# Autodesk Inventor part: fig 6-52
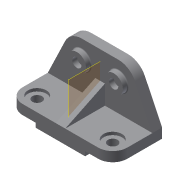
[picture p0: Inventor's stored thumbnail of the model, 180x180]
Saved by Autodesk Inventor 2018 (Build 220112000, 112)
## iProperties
Shininess: 77.0
Length Units: 11269
Angle Units: 11279
Time Units: 11290
Mass Units: 11283
Length Display Precision: 3
Angle Display Precision: 2
Created: 2001-12
Part Number: fig 6-52
Document SubType Name: Modeling
Designer: Renu Muthoo
Density: 1 g/cm^3
Material: Generic
Appearance: Default
Density: 0.0
Volumn: 0.0
Area: 0.0
PropertySet Name: Model Information
Control State: 0
Master: False
Checked Out: False
Author: Renu Muthoo
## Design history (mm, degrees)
node "Sketch1"
sketch "Sketch2"
  geometry: L1 (-67.219, 19.116)-(148.781, 19.116); L2 (148.781, 19.116)-(148.781, -0.884); L3 (-67.219, -0.884)-(-67.219, 19.116); L4 (-10.219, -0.884)-(-10.219, -9.884); L5 (-10.219, -9.884)-(91.781, -9.884); L6 (91.781, -9.884)-(91.781, -0.884); L7 (148.781, -0.884)-(91.781, -0.884); L8 (-10.219, -0.884)-(-67.219, -0.884)
  constraints: 16 end point, 5 parallel, 4 perpendicular, 2 equal length, 1 horizontal
  dimensions: "d0" = 102 distance of L4.end L5.end; "d1" = 57 distance of L4.start L3.start; "d2" = 29 distance between parallel lines of L1 L5; "d3" = 20 distance of L1.end L2.end
extrude "Extrusion1" new body sketch "Sketch2" distance "d4" = 102; taper "d5" = 0 deg
sketch "Sketch3"
  geometry: L1 (67.219, -19.116)-(-148.781, -19.116) reference; L2 (67.219, -19.116)-(31.475, -93.564); L3 (-2.781, -115.116)-(-78.781, -115.116); L4 (-113.038, -93.564)-(-148.781, -19.116); A1 r 38 centre (-2.781, -77.116) between (-2.781, -115.116) and (31.475, -93.564); A2 r 38 centre (-78.781, -77.116) between (-113.038, -93.564) and (-78.781, -115.116)
  constraints: 6 end point, 4 point on circle, 4 tangent, 2 centre point, 1 equal length, 1 equal radius, 1 parallel
  dimensions: "d6" = 96 distance between parallel lines of L3 L1; "d7" = 38 radius of A1; "d8" = 76 distance of A2.centre A1.centre
extrude "Extrusion2" join sketch "Sketch3" distance "d9" = 20; taper "d10" = 0 deg
fillet "Fillet1" dims "d11" = 30
workplane "Work Plane1"
sketch "Sketch5"
  geometry: A1 r 30 centre (-30, 0) between (-30, -30) and (0, 0) reference; 1 further point
  constraints: 1 coincident
hole "Hole1" sketch "Sketch5" at (-30, 0) diameter "d16" = 20; stored, may be unused: countersink angle "d20" = 82 deg, drill point angle "d22" = 118 deg; dims "d17" = 6, "d18" = 38, "d19" = 6, "d21" = 8
sketch "Sketch6"
  geometry: C1 r 19 at (-2.781, 77.116); C2 r 9.5 at (-2.781, 77.116); A1 r 38 centre (-2.781, 77.116) between (31.475, 93.564) and (-2.781, 115.116) reference
  constraints: 2 centre point, 2 coincident
  dimensions: "d23" = 38 diameter of C1; "d24" = 19 diameter of C2
extrude "Extrusion3" join sketch "Sketch6" distance "d25" = 10; taper "d26" = 0 deg
sketch "Sketch7"
  geometry: L1 (0, -82)-(-39.557, 0); L2 (0, -82)-(20, -82) reference; L3 (29, 22.405)-(29, -82); L4 (29, -82)-(0, -82); L5 (0, -82)-(0, 0); L6 (0, 0)-(-90.034, 0); L7 (-90.034, 0)-(-90.034, 22.405); L8 (-90.034, 22.405)-(29, 22.405); L9 (0, 0)-(-74.447, 0) reference
  constraints: 14 end point, 1 collinear, 1 point on line
feature "Rib3" sketch "Sketch7" dims "d35" = 10, "d36" = 20
fillet "Fillet3" dims "d37" = 2
mirror "Mirror4"
body "Solid1"
other parameters: "d12" = -108
